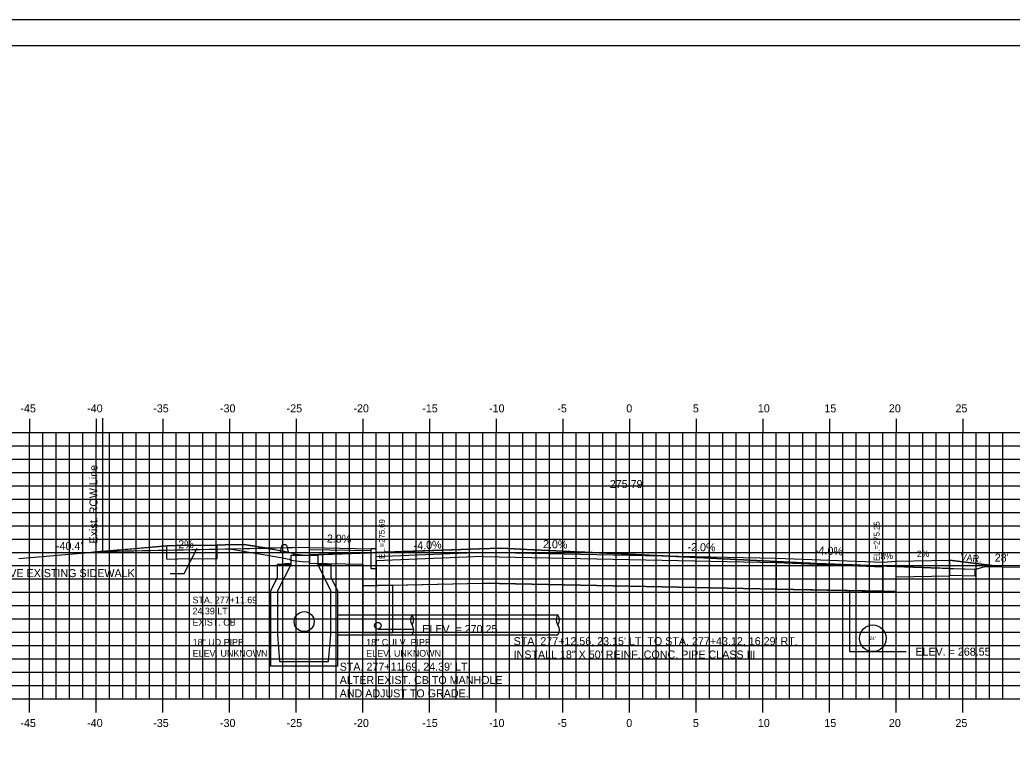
# Model space of a CAD drawing. Extents: x 854008 to 854178, y 366268 to 366378.
# Drawn here: x 854045.4 to 854119.8, y 366324.1 to 366378.2 of the extents above; entities that cross this region are included whole.
import ezdxf

# ---------------------------------------------------------------- set-up
doc = ezdxf.new("R2010")
doc.units = 0
for name, color, linetype in [('ANNOTATION', 7, 'Continuous'), ('BORDER', 7, 'Continuous'), ('D_Curb_Type_1_Lt', 7, 'Continuous'), ('D_Drainage_Culvert', 7, 'Continuous'), ('D_Drainage_Text', 7, 'Continuous'), ('D_Roadway_Centerline_Text', 7, 'Continuous'), ('D_Roadway_Drive_Gravel_RT', 7, 'Continuous'), ('D_Roadway_Drive_SubGrade', 7, 'Continuous'), ('D_Roadway_Edge_TW', 7, 'Continuous'), ('D_Roadway_FinishedGrade', 7, 'Continuous'), ('D_Roadway_Sidewalks_Paved', 7, 'Continuous'), ('D_Roadway_SubGrade', 7, 'Continuous'), ('D_Text_Monospaced', 7, 'Continuous'), ('D_Text_Standard', 7, 'Continuous'), ('E_ROW_Line', 7, 'Continuous'), ('H_V ANNOTATION', 7, 'Continuous'), ('JUNK COM EXC', 7, 'Continuous'), ('JUNK FILL', 7, 'Continuous'), ('junk strct exc', 7, 'Continuous'), ('MAJOR', 7, 'Continuous'), ('MINOR', 7, 'Continuous'), ('PDRAIN', 7, 'Continuous'), ('PDRAINTXT', 7, 'Continuous'), ('PLOT BOUNDARY', 7, 'Continuous'), ('S_Curb_Type_3', 7, 'Continuous'), ('S_Drainage_CB', 7, 'Continuous'), ('S_Drainage_Culvert_Top', 7, 'Continuous'), ('S_Roadway_Centerline', 7, 'Continuous')]:
    doc.layers.add(name, color=color, linetype=linetype)

msp = doc.modelspace()

# ---------------------------------------------------------------- linework, layer by layer
at = {"layer": 'ANNOTATION'}
msp.add_lwpolyline([(854056.648, 366336.645), (854057.708, 366336.645), (854058.676, 366338.552)], dxfattribs=at)
at = {"layer": 'BORDER'}
msp.add_line((854176.103, 366376.236), (854016.103, 366376.236), dxfattribs=at)
at = {"layer": 'D_Curb_Type_1_Lt'}
msp.add_lwpolyline([(854071.692, 366338.511), (854071.692, 366337.011), (854072.108, 366337.011), (854072.108, 366338.511)], close=True, dxfattribs=at)
at = {"layer": 'D_Drainage_Culvert'}
msp.add_line((854069.194, 366333.536), (854085.729, 366333.536), dxfattribs=at)
msp.add_lwpolyline([(854069.194, 366332.036), (854074.792, 366332.036), (854085.729, 366332.036)], dxfattribs=at)
for centre, radius, start, end in [((854086.229, 366333.161), 0.625, 143.1301, 216.8699), ((854085.235, 366333.163), 0.619, 322.63527, 37.06098), ((854085.231, 366332.411), 0.623, 322.99362, 36.92245)]:
    msp.add_arc(centre, radius, start, end, dxfattribs=at)
at = {"layer": 'D_Roadway_Drive_Gravel_RT'}
for p, q in [((854110.099, 366337.487), (854111.099, 366337.567)), ((854111.099, 366337.567), (854115.099, 366337.647)), ((854111.099, 366336.4), (854115.099, 366336.48))]:
    msp.add_line(p, q, dxfattribs=at)
at = {"layer": 'D_Roadway_Drive_SubGrade'}
for p, q in [((854111.103, 366335.294), (854111.099, 366336.4)), ((854110.103, 366335.314), (854111.103, 366335.294))]:
    msp.add_line(p, q, dxfattribs=at)
at = {"layer": 'D_Roadway_Edge_TW'}
for points in [[(854072.103, 366337.927), (854080.103, 366338.247), (854102.103, 366337.807), (854110.103, 366337.487)], [(854072.103, 366337.927), (854080.103, 366338.247), (854102.103, 366337.807), (854110.099, 366337.487)]]:
    msp.add_lwpolyline(points, dxfattribs=at)
at = {"layer": 'D_Roadway_FinishedGrade'}
for p, q in [((854067.103, 366338.602), (854051.996, 366338.3)), ((854115.099, 366337.647), (854115.099, 366336.48))]:
    msp.add_line(p, q, dxfattribs=at)
msp.add_lwpolyline([(854115.099, 366337.647), (854119.103, 366337.139)], dxfattribs=at)
msp.add_arc((854052.396, 366318.304), 20, 91.14576, 94.76907, dxfattribs=at)
at = {"layer": 'D_Roadway_Sidewalks_Paved'}
msp.add_lwpolyline([(854067.103, 366338.602), (854071.692, 366338.511), (854071.692, 366338.344), (854067.103, 366338.436)], close=True, dxfattribs=at)
at = {"layer": 'D_Roadway_SubGrade'}
for p, q in [((854067.103, 366337.435), (854067.103, 366338.436)), ((854110.103, 366337.154), (854110.103, 366337.487)), ((854117.021, 366336.48), (854117.021, 366336.98))]:
    msp.add_line(p, q, dxfattribs=at)
for points in [[(854061.253, 366338.485), (854065.105, 366337.827), (854065.425, 366337.759), (854065.591, 366337.719), (854065.666, 366337.654), (854066.774, 366337.524), (854067.103, 366337.536)], [(854067.103, 366337.435), (854071.103, 366337.355), (854071.103, 366335.734), (854072.103, 366335.754)], [(854115.103, 366336.534), (854117.021, 366336.48)]]:
    msp.add_lwpolyline(points, dxfattribs=at)
for points in [[(854080.103, 366337.914), (854072.103, 366337.594), (854072.103, 366335.754), (854080.103, 366335.914)], [(854080.103, 366335.914), (854080.103, 366337.914), (854091.103, 366337.694), (854102.103, 366337.474), (854102.103, 366335.474), (854091.103, 366335.694)], [(854102.103, 366337.474), (854110.103, 366337.154), (854110.103, 366335.314), (854102.103, 366335.474)]]:
    msp.add_lwpolyline(points, close=True, dxfattribs=at)
at = {"layer": 'D_Text_Standard'}
for points in [[(854072.228, 366332.483), (854074.196, 366332.483), (854074.876, 366332.483)], [(854111.103, 366330.786), (854111.18, 366330.786), (854111.86, 366330.786)]]:
    msp.add_lwpolyline(points, dxfattribs=at)
at = {"layer": 'E_ROW_Line'}
msp.add_line((854051.6, 366338.307), (854051.6, 366348.307), dxfattribs=at)
at = {"layer": 'JUNK COM EXC'}
msp.add_lwpolyline([(854051.425, 366338.293), (854063.91, 366338.538), (854062.199, 366338.831), (854060.788, 366338.79), (854060.085, 366338.77), (854058.685, 366338.76), (854057.203, 366338.744), (854056.809, 366338.73), (854056.415, 366338.717), (854053.92, 366338.505)], close=True, dxfattribs=at)
msp.add_lwpolyline([(854067.103, 366338.037), (854067.103, 366337.435), (854071.103, 366337.355), (854071.103, 366335.734), (854080.103, 366335.914), (854102.103, 366335.474), (854111.103, 366335.294), (854111.099, 366336.4), (854115.099, 366336.48), (854115.103, 366337.034), (854113.696, 366337.074), (854111.099, 366337.173), (854105.15, 366337.4), (854098.162, 366337.752), (854092.093, 366338.048), (854083.395, 366338.452), (854081.97, 366338.519), (854081.426, 366338.543), (854079.864, 366338.503), (854067.103, 366338.037)], dxfattribs=at)
at = {"layer": 'JUNK FILL'}
for points in [[(854067.103, 366338.037), (854067.103, 366338.602), (854063.91, 366338.538), (854065.199, 366338.318), (854065.535, 366338.246), (854065.827, 366338.177), (854065.878, 366338.132), (854066.794, 366338.025), (854067.103, 366338.037)], [(854115.103, 366337.034), (854117.106, 366336.977), (854117.575, 366337.134), (854117.84, 366337.181), (854119.066, 366337.139), (854119.103, 366337.139), (854115.103, 366337.646), (854115.103, 366337.034)]]:
    msp.add_lwpolyline(points, dxfattribs=at)
at = {"layer": 'junk strct exc'}
for points in [[(854071.103, 366335.734), (854071.103, 366332.233), (854073.353, 366332.233), (854073.353, 366335.779)], [(854107.603, 366335.364), (854107.603, 366330.786), (854111.103, 366330.786), (854111.103, 366335.294)]]:
    msp.add_lwpolyline(points, close=True, dxfattribs=at)
at = {"layer": 'MAJOR'}
for p, q in [((854046.103, 366348.238), (854046.103, 366347.236)), ((854051.103, 366348.238), (854051.103, 366347.236)), ((854056.103, 366348.238), (854056.103, 366347.236)), ((854061.103, 366348.238), (854061.103, 366347.236)), ((854066.103, 366348.238), (854066.103, 366347.236)), ((854071.103, 366348.238), (854071.103, 366347.236)), ((854076.103, 366348.238), (854076.103, 366347.236)), ((854081.103, 366348.238), (854081.103, 366347.236)), ((854086.103, 366348.238), (854086.103, 366347.236)), ((854091.103, 366348.238), (854091.103, 366347.236)), ((854096.103, 366348.238), (854096.103, 366347.236)), ((854101.103, 366348.238), (854101.103, 366347.236)), ((854106.103, 366348.238), (854106.103, 366347.236)), ((854111.103, 366348.238), (854111.103, 366347.236)), ((854116.103, 366348.238), (854116.103, 366347.236)), ((854021.103, 366347.236), (854161.103, 366347.236)), ((854021.103, 366347.236), (854161.103, 366347.236)), ((854046.103, 366327.236), (854046.103, 366347.236)), ((854051.103, 366327.236), (854051.103, 366347.236)), ((854056.103, 366327.236), (854056.103, 366347.236)), ((854061.103, 366327.236), (854061.103, 366347.236)), ((854066.103, 366327.236), (854066.103, 366347.236)), ((854071.103, 366327.236), (854071.103, 366347.236)), ((854076.103, 366327.236), (854076.103, 366347.236)), ((854081.103, 366327.236), (854081.103, 366347.236)), ((854086.103, 366327.236), (854086.103, 366347.236)), ((854091.103, 366327.236), (854091.103, 366347.236)), ((854096.103, 366327.236), (854096.103, 366347.236)), ((854101.103, 366327.236), (854101.103, 366347.236)), ((854106.103, 366327.236), (854106.103, 366347.236)), ((854111.103, 366327.236), (854111.103, 366347.236)), ((854116.103, 366327.236), (854116.103, 366347.236)), ((854021.103, 366342.236), (854161.103, 366342.236)), ((854021.103, 366337.236), (854161.103, 366337.236)), ((854021.103, 366332.236), (854161.103, 366332.236)), ((854021.103, 366327.236), (854161.103, 366327.236)), ((854021.103, 366327.236), (854161.103, 366327.236)), ((854046.103, 366326.234), (854046.103, 366327.236)), ((854051.103, 366326.234), (854051.103, 366327.236)), ((854056.103, 366326.234), (854056.103, 366327.236)), ((854061.103, 366326.234), (854061.103, 366327.236)), ((854066.103, 366326.234), (854066.103, 366327.236)), ((854071.103, 366326.234), (854071.103, 366327.236)), ((854076.103, 366326.234), (854076.103, 366327.236)), ((854081.103, 366326.234), (854081.103, 366327.236)), ((854086.103, 366326.234), (854086.103, 366327.236)), ((854091.103, 366326.234), (854091.103, 366327.236)), ((854096.103, 366326.234), (854096.103, 366327.236)), ((854101.103, 366326.234), (854101.103, 366327.236)), ((854106.103, 366326.234), (854106.103, 366327.236)), ((854111.103, 366326.234), (854111.103, 366327.236)), ((854116.103, 366326.234), (854116.103, 366327.236))]:
    msp.add_line(p, q, dxfattribs=at)
at = {"layer": 'MINOR'}
for p, q in [((854047.103, 366327.236), (854047.103, 366347.236)), ((854048.103, 366327.236), (854048.103, 366347.236)), ((854049.103, 366327.236), (854049.103, 366347.236)), ((854050.103, 366327.236), (854050.103, 366347.236)), ((854052.103, 366327.236), (854052.103, 366347.236)), ((854053.103, 366327.236), (854053.103, 366347.236)), ((854054.103, 366327.236), (854054.103, 366347.236)), ((854055.103, 366327.236), (854055.103, 366347.236)), ((854057.103, 366327.236), (854057.103, 366347.236)), ((854058.103, 366327.236), (854058.103, 366347.236)), ((854059.103, 366327.236), (854059.103, 366347.236)), ((854060.103, 366327.236), (854060.103, 366347.236)), ((854062.103, 366327.236), (854062.103, 366347.236)), ((854063.103, 366327.236), (854063.103, 366347.236)), ((854064.103, 366327.236), (854064.103, 366347.236)), ((854065.103, 366327.236), (854065.103, 366347.236)), ((854067.103, 366327.236), (854067.103, 366347.236)), ((854068.103, 366327.236), (854068.103, 366347.236)), ((854069.103, 366327.236), (854069.103, 366347.236)), ((854070.103, 366327.236), (854070.103, 366347.236)), ((854072.103, 366327.236), (854072.103, 366347.236)), ((854073.103, 366327.236), (854073.103, 366347.236)), ((854074.103, 366327.236), (854074.103, 366347.236)), ((854075.103, 366327.236), (854075.103, 366347.236)), ((854077.103, 366327.236), (854077.103, 366347.236)), ((854078.103, 366327.236), (854078.103, 366347.236)), ((854079.103, 366327.236), (854079.103, 366347.236)), ((854080.103, 366327.236), (854080.103, 366347.236)), ((854082.103, 366327.236), (854082.103, 366347.236)), ((854083.103, 366327.236), (854083.103, 366347.236)), ((854084.103, 366327.236), (854084.103, 366347.236)), ((854085.103, 366327.236), (854085.103, 366347.236)), ((854087.103, 366327.236), (854087.103, 366347.236)), ((854088.103, 366327.236), (854088.103, 366347.236)), ((854089.103, 366327.236), (854089.103, 366347.236)), ((854090.103, 366327.236), (854090.103, 366347.236)), ((854092.103, 366327.236), (854092.103, 366347.236)), ((854093.103, 366327.236), (854093.103, 366347.236)), ((854094.103, 366327.236), (854094.103, 366347.236)), ((854095.103, 366327.236), (854095.103, 366347.236)), ((854097.103, 366327.236), (854097.103, 366347.236)), ((854098.103, 366327.236), (854098.103, 366347.236)), ((854099.103, 366327.236), (854099.103, 366347.236)), ((854100.103, 366327.236), (854100.103, 366347.236)), ((854102.103, 366327.236), (854102.103, 366347.236)), ((854103.103, 366327.236), (854103.103, 366347.236)), ((854104.103, 366327.236), (854104.103, 366347.236)), ((854105.103, 366327.236), (854105.103, 366347.236)), ((854107.103, 366327.236), (854107.103, 366347.236)), ((854108.103, 366327.236), (854108.103, 366347.236)), ((854109.103, 366327.236), (854109.103, 366347.236)), ((854110.103, 366327.236), (854110.103, 366347.236)), ((854112.103, 366327.236), (854112.103, 366347.236)), ((854113.103, 366327.236), (854113.103, 366347.236)), ((854114.103, 366327.236), (854114.103, 366347.236)), ((854115.103, 366327.236), (854115.103, 366347.236)), ((854117.103, 366327.236), (854117.103, 366347.236)), ((854118.103, 366327.236), (854118.103, 366347.236)), ((854119.103, 366327.236), (854119.103, 366347.236)), ((854021.103, 366346.236), (854161.103, 366346.236)), ((854021.103, 366345.236), (854161.103, 366345.236)), ((854021.103, 366344.236), (854161.103, 366344.236)), ((854021.103, 366343.236), (854161.103, 366343.236)), ((854021.103, 366341.236), (854161.103, 366341.236)), ((854021.103, 366340.236), (854161.103, 366340.236)), ((854021.103, 366339.236), (854161.103, 366339.236)), ((854021.103, 366338.236), (854161.103, 366338.236)), ((854021.103, 366336.236), (854161.103, 366336.236)), ((854021.103, 366335.236), (854161.103, 366335.236)), ((854021.103, 366334.236), (854161.103, 366334.236)), ((854021.103, 366333.236), (854161.103, 366333.236)), ((854021.103, 366331.236), (854161.103, 366331.236)), ((854021.103, 366330.236), (854161.103, 366330.236)), ((854021.103, 366329.236), (854161.103, 366329.236)), ((854021.103, 366328.236), (854161.103, 366328.236))]:
    msp.add_line(p, q, dxfattribs=at)
at = {"layer": 'PDRAIN'}
for points in [[(854071.103, 366335.734), (854071.103, 366332.233), (854073.353, 366332.233), (854073.353, 366335.734)], [(854107.603, 366335.364), (854107.603, 366330.786), (854111.103, 366330.786), (854111.103, 366335.294)]]:
    msp.add_lwpolyline(points, dxfattribs=at)
for centre, radius in [((854072.228, 366332.733), 0.25), ((854109.353, 366331.786), 1)]:
    msp.add_circle(centre, radius, dxfattribs=at)
at = {"layer": 'PLOT BOUNDARY'}
msp.add_lwpolyline([(854008.01, 366268.177), (854178.01, 366268.177), (854178.01, 366378.177), (854008.01, 366378.177)], close=True, dxfattribs=at)
at = {"layer": 'S_Curb_Type_3'}
for points in [[(854065.013, 366338.691), (854064.91, 366338.246), (854065.535, 366338.246), (854065.432, 366338.691)], [(854065.31, 366338.788), (854065.134, 366338.788)]]:
    msp.add_lwpolyline(points, dxfattribs=at)
for centre, start, end in [((854065.134, 366338.663), 90, 167.00538), ((854065.31, 366338.663), 12.99462, 90)]:
    msp.add_arc(centre, 0.125, start, end, dxfattribs=at)
at = {"layer": 'S_Drainage_CB'}
for p, q in [((854064.699, 366336.368), (854064.699, 366337.352)), ((854064.699, 366337.352), (854065.716, 366337.352)), ((854065.716, 366337.352), (854064.699, 366335.351)), ((854067.717, 366337.352), (854068.702, 366337.352)), ((854068.702, 366335.351), (854067.717, 366337.352)), ((854068.702, 366337.352), (854068.702, 366336.368)), ((854064.207, 366335.351), (854064.699, 366336.368)), ((854068.702, 366336.368), (854069.194, 366335.351)), ((854064.207, 366329.708), (854064.207, 366335.351)), ((854064.699, 366335.351), (854064.699, 366332.037)), ((854068.702, 366332.037), (854068.702, 366335.351)), ((854069.194, 366335.351), (854069.194, 366329.708)), ((854064.699, 366332.037), (854064.863, 366330.036)), ((854068.538, 366330.036), (854068.702, 366332.037)), ((854069.194, 366329.708), (854064.207, 366329.708)), ((854064.863, 366330.036), (854068.538, 366330.036))]:
    msp.add_line(p, q, dxfattribs=at)
msp.add_lwpolyline([(854065.224, 366337.394), (854065.716, 366337.394), (854065.716, 366338.017), (854067.717, 366338.017), (854067.717, 366337.394), (854068.21, 366337.394)], dxfattribs=at)
at = {"layer": 'S_Drainage_Culvert_Top'}
for p, q in [((854069.194, 366333.536), (854074.792, 366333.536)), ((854069.194, 366332.036), (854074.792, 366332.036))]:
    msp.add_line(p, q, dxfattribs=at)
msp.add_circle((854066.7, 366333.036), 0.75, dxfattribs=at)
for centre, start, end in [((854075.292, 366333.161), 143.1301, 216.8699), ((854074.292, 366333.161), 323.1301, 36.8699), ((854074.292, 366332.411), 323.1301, 36.8699)]:
    msp.add_arc(centre, 0.625, start, end, dxfattribs=at)
at = {"layer": 'S_Roadway_Centerline'}
for p, q in [((854056.415, 366337.716), (854056.415, 366338.717)), ((854060.166, 366337.777), (854060.166, 366338.777))]:
    msp.add_line(p, q, dxfattribs=at)
for points in [[(854045.291, 366337.781), (854051.425, 366338.293), (854056.415, 366338.717), (854057.203, 366338.744), (854060.166, 366338.777), (854060.788, 366338.79), (854062.199, 366338.831), (854065.199, 366338.318), (854065.535, 366338.246), (854065.827, 366338.177), (854065.878, 366338.132), (854066.794, 366338.025), (854079.864, 366338.503), (854081.426, 366338.543), (854081.97, 366338.519), (854083.395, 366338.452), (854092.093, 366338.048), (854098.162, 366337.752), (854105.15, 366337.4), (854113.696, 366337.074), (854117.106, 366336.977), (854117.575, 366337.134), (854117.84, 366337.181), (854119.066, 366337.139), (854120.534, 366337.135)], [(854056.415, 366337.716), (854057.226, 366337.744), (854060.166, 366337.777)]]:
    msp.add_lwpolyline(points, dxfattribs=at)

# ---------------------------------------------------------------- texts
at = {"layer": 'ANNOTATION'}
for s, rotation, p in [('2.0%', 358.85423, (854068.401, 366338.977)), ('-2%', 0.72739, (854056.995, 366338.531)), ('-4.0%', 2.29063, (854074.924, 366338.441)), ('2.0%', 358.85423, (854084.611, 366338.557)), ('-2.0%', 358.85423, (854095.45, 366338.341)), ('-4.0%', 357.7096, (854105.003, 366338.092))]:
    msp.add_text(s, height=0.6, rotation=rotation, dxfattribs=at).set_placement(p)
msp.add_text('REMOVE EXISTING SIDEWALK', height=0.6, dxfattribs=at).set_placement((854042.182, 366336.378))
at = {"layer": 'D_Drainage_Text'}
for s, p in [("STA. 277+12.56, 23.15' LT. TO STA. 277+43.12, 16.29' RT.", (854082.411, 366331.272)), ('INSTALL 18" X 50\' REINF. CONC. PIPE CLASS III', (854082.411, 366330.272)), ("STA. 277+11.69, 24.39' LT.", (854069.367, 366329.359)), ('ALTER EXIST. CB TO MANHOLE', (854069.367, 366328.359)), ('AND ADJUST TO GRADE.', (854069.367, 366327.359))]:
    msp.add_text(s, height=0.6, dxfattribs=at).set_placement(p)
at = {"layer": 'D_Roadway_Centerline_Text'}
msp.add_text('275.79', height=0.6, dxfattribs=at).set_placement((854089.626, 366343.059))
at = {"layer": 'D_Roadway_Drive_Gravel_RT'}
for s, rotation, p in [('8%', 4.57392, (854109.946, 366337.68)), ('2%', 1.19222, (854112.661, 366337.876))]:
    msp.add_text(s, height=0.48, rotation=rotation, dxfattribs=at).set_placement(p)
at = {"layer": 'D_Text_Monospaced'}
for s, height, p in [('STA. 277+11.69', 0.49998, (854058.328, 366334.412)), ('24.39 LT.', 0.5, (854058.328, 366333.578)), ('EXIST. CB', 0.5, (854058.328, 366332.738))]:
    msp.add_text(s, height=height, dxfattribs=at).set_placement(p)
at = {"layer": 'D_Text_Standard'}
for s, height, rotation, p in [(' EL.=275.69', 0.4335, 90, (854072.747, 366337.581)), (' EL.=275.25', 0.4335, 90, (854109.858, 366337.418)), ('VAR.', 0.51, 353.12613, (854115.907, 366337.65))]:
    msp.add_text(s, height=height, rotation=rotation, dxfattribs=at).set_placement(p)
for s, p in [("-40.4'", (854048.088, 366338.418)), ("28'", (854118.495, 366337.541)), ('ELEV. = 270.25', (854075.556, 366332.183)), ('ELEV. = 268.55', (854112.54, 366330.486))]:
    msp.add_text(s, height=0.6, dxfattribs=at).set_placement(p)
at = {"layer": 'E_ROW_Line'}
msp.add_text('Exist. ROW Line', height=0.6, rotation=90, dxfattribs=at).set_placement((854051.2, 366338.907))
at = {"layer": 'H_V ANNOTATION'}
for s, p in [('-45', (854045.421, 366348.736)), ('-40', (854050.429, 366348.736)), ('-35', (854055.383, 366348.736)), ('-30', (854060.391, 366348.736)), ('-25', (854065.389, 366348.736)), ('-20', (854070.397, 366348.736)), ('-15', (854075.56, 366348.736)), ('-10', (854080.568, 366348.736)), ('-5', (854085.694, 366348.736)), ('0', (854090.862, 366348.736)), ('5', (854095.854, 366348.736)), ('10', (854100.728, 366348.736)), ('15', (854105.72, 366348.736)), ('20', (854110.557, 366348.736)), ('25', (854115.549, 366348.736)), ('-45', (854045.421, 366325.136)), ('-40', (854050.429, 366325.136)), ('-35', (854055.383, 366325.136)), ('-30', (854060.391, 366325.136)), ('-25', (854065.389, 366325.136)), ('-20', (854070.397, 366325.136)), ('-15', (854075.56, 366325.136)), ('-10', (854080.568, 366325.136)), ('-5', (854085.694, 366325.136)), ('0', (854090.862, 366325.136)), ('5', (854095.854, 366325.136)), ('10', (854100.728, 366325.136)), ('15', (854105.72, 366325.136)), ('20', (854110.557, 366325.136)), ('25', (854115.549, 366325.136))]:
    msp.add_text(s, height=0.6, dxfattribs=at).set_placement(p)
at = {"layer": 'PDRAIN'}
msp.add_text('24"', height=0.25, dxfattribs=at).set_placement((854109.111, 366331.661))
at = {"layer": 'PDRAINTXT'}
for s, p in [('18" UD PIPE', (854058.343, 366331.242)), ('18" CULV. PIPE', (854071.357, 366331.242)), ('ELEV. UNKNOWN', (854058.343, 366330.409)), ('ELEV. UNKNOWN', (854071.357, 366330.409))]:
    msp.add_text(s, height=0.5, dxfattribs=at).set_placement(p)
at = {"layer": 'S_Roadway_Centerline'}
for s, p in [('C', (854092.088, 366338.048)), ('L', (854092.093, 366338.041))]:
    msp.add_text(s, height=0.0146, dxfattribs=at).set_placement(p)

doc.saveas('drawing.dxf')
